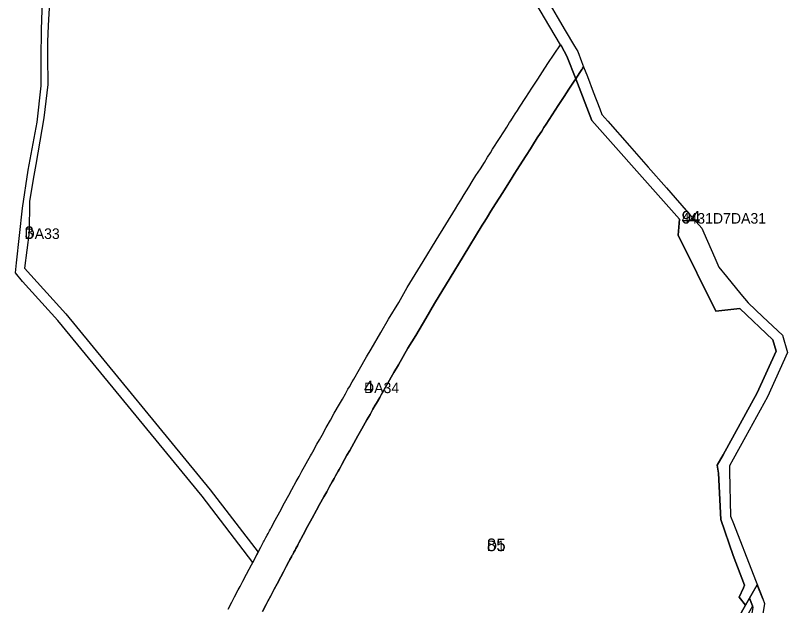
# Model space of a CAD drawing. Extents: x -537012 to -534603, y -1176562 to -1172739.
# Drawn here: x -536018.6 to -535651.7, y -1173694.5 to -1173413.8 of the extents above; entities that cross this region are included whole.
import ezdxf

# ---------------------------------------------------------------- set-up
doc = ezdxf.new("R2010")
doc.units = 0
for name, color, linetype in [('96120023', 7, 'Continuous'), ('96140023', 7, 'Continuous'), ('ID_VPO', 7, 'Continuous'), ('ID_VPS', 7, 'Continuous')]:
    doc.layers.add(name, color=color, linetype=linetype)

msp = doc.modelspace()

# ---------------------------------------------------------------- linework, layer by layer
at = {"layer": '96120023'}
for points in [[(-535666.09, -1173684.66), (-535668.4, -1173688.75), (-535669.68, -1173691), (-535671.6, -1173694.36), (-535674.68, -1173690.42), (-535672.65, -1173686.12), (-535672.1, -1173684.83), (-535677.54, -1173670.61), (-535683.41, -1173653.53), (-535684.54, -1173631.55), (-535685.07, -1173627.77), (-535682.21, -1173622.82), (-535666.13, -1173593.26), (-535657.03, -1173573.52), (-535658.57, -1173568.09), (-535674.26, -1173553.24), (-535685.71, -1173554.4), (-535703.6, -1173518.27), (-535703.03, -1173510.68), (-535711.9, -1173500.73), (-535744.67, -1173463.76), (-535752.34, -1173443.92), (-535751.46, -1173442.6), (-535750.38, -1173440.96), (-535749.69, -1173439.9), (-535749.4, -1173439.46), (-535749.18, -1173439.12), (-535749.05, -1173438.92), (-535748.57, -1173438.22), (-535746.8, -1173442.83), (-535744, -1173450.12), (-535740.92, -1173458.17), (-535739.9, -1173460.82), (-535737.04, -1173464.08), (-535726.71, -1173475.86), (-535717.86, -1173485.95), (-535709.19, -1173495.84), (-535697.78, -1173508.85), (-535692.41, -1173514.97), (-535691.44, -1173517.18), (-535686.26, -1173529.03), (-535684.28, -1173533.55), (-535680.66, -1173537.97), (-535673.84, -1173546.31), (-535670.41, -1173550.5), (-535663.43, -1173557.09), (-535654.08, -1173565.9), (-535651.65, -1173574.09), (-535661.19, -1173595.23), (-535671.63, -1173614.14), (-535677.56, -1173624.89), (-535679.29, -1173628.03), (-535679.23, -1173630.64), (-535678.7, -1173651.88), (-535677.33, -1173655.42), (-535668, -1173679.5), (-535663.42, -1173691.33)], [(-535686.92, -1173727.29), (-535695.05, -1173742.16), (-535697.41, -1173740.24), (-535689.54, -1173725.83), (-535671.6, -1173694.36), (-535669.68, -1173691), (-535668.29, -1173694.6), (-535668.99, -1173695.85)]]:
    msp.add_lwpolyline(points, close=True, dxfattribs=at)
msp.add_lwpolyline([(-535901.19, -1173697.3), (-535899.47, -1173694.01), (-535898.61, -1173692.37), (-535897.31, -1173689.9), (-535895.58, -1173686.61), (-535894.28, -1173684.14), (-535892.54, -1173680.85), (-535891.24, -1173678.38), (-535889.92, -1173675.92), (-535888.62, -1173673.46), (-535888.61, -1173673.44), (-535888.6, -1173673.43), (-535888.59, -1173673.41), (-535888.59, -1173673.4), (-535888.58, -1173673.4), (-535888.58, -1173673.39), (-535888.58, -1173673.38), (-535888.57, -1173673.37), (-535888.56, -1173673.35), (-535888.56, -1173673.34), (-535888.55, -1173673.33), (-535888.16, -1173672.6), (-535887.91, -1173672.13), (-535887.71, -1173671.75), (-535887.43, -1173671.24), (-535887.21, -1173670.83), (-535887.04, -1173670.5), (-535886.84, -1173670.13), (-535886.68, -1173669.83), (-535886.46, -1173669.43), (-535886.31, -1173669.14), (-535885.72, -1173668.05), (-535885.31, -1173667.27), (-535884.96, -1173666.61), (-535884.64, -1173666.01), (-535884.21, -1173665.24), (-535883.86, -1173664.58), (-535881.86, -1173660.91), (-535879.78, -1173656.88), (-535877.58, -1173652.84), (-535875.5, -1173649.17), (-535874.03, -1173646.36), (-535872.01, -1173642.75), (-535870.7, -1173640.37), (-535869.29, -1173637.83), (-535868.07, -1173635.6), (-535867.21, -1173634.07), (-535866.5, -1173632.73), (-535865.29, -1173630.57), (-535864.82, -1173629.72), (-535864.19, -1173628.6), (-535863.82, -1173627.94), (-535863.5, -1173627.33), (-535862.2, -1173625.07), (-535861.04, -1173622.93), (-535859.76, -1173620.67), (-535857.86, -1173617.18), (-535855.84, -1173613.7), (-535854.01, -1173610.34), (-535851.56, -1173606.18), (-535850.1, -1173603.55), (-535848.69, -1173601.04), (-535847.65, -1173599.15), (-535847.04, -1173598.17), (-535845.5, -1173595.47), (-535844.79, -1173594.23), (-535842.03, -1173589.46), (-535838.73, -1173583.65), (-535836.59, -1173579.98), (-535832.07, -1173572.1), (-535828.4, -1173565.98), (-535823.51, -1173557.91), (-535819.48, -1173550.82), (-535812.02, -1173538.6), (-535805.78, -1173528.45), (-535796.72, -1173513.55), (-535795.59, -1173511.7), (-535794.26, -1173509.57), (-535792.64, -1173506.93), (-535790.41, -1173503.44), (-535788.7, -1173500.63), (-535787.04, -1173497.94), (-535784.97, -1173494.7), (-535783.04, -1173491.61), (-535781.54, -1173489.23), (-535780.2, -1173487.12), (-535779.1, -1173485.35), (-535775.95, -1173480.36), (-535773.9, -1173477.22), (-535772.4, -1173474.86), (-535771.12, -1173472.81), (-535770.58, -1173471.97), (-535769.29, -1173469.99), (-535768.51, -1173468.76), (-535767.41, -1173467.11), (-535766.37, -1173465.46), (-535763.47, -1173460.97), (-535760.66, -1173456.57), (-535757.85, -1173452.35), (-535755.58, -1173448.83), (-535753.05, -1173444.98), (-535752.34, -1173443.92), (-535744.67, -1173463.76), (-535711.9, -1173500.73), (-535703.03, -1173510.68), (-535703.6, -1173518.27), (-535685.71, -1173554.4), (-535674.26, -1173553.24), (-535658.57, -1173568.09), (-535657.03, -1173573.52), (-535666.13, -1173593.26), (-535682.21, -1173622.82), (-535685.07, -1173627.77), (-535684.54, -1173631.55), (-535683.41, -1173653.53), (-535677.54, -1173670.61), (-535672.1, -1173684.83), (-535672.65, -1173686.12), (-535674.68, -1173690.42), (-535671.6, -1173694.36), (-535689.54, -1173725.83)], dxfattribs=at)
at = {"layer": '96140023'}
for points in [[(-536002.3, -1173404.63), (-536002.99, -1173418.53), (-536003.38, -1173426.31), (-536003.35, -1173433.33), (-536003.3, -1173446.59), (-536005.11, -1173462.48), (-536008.94, -1173484.69), (-536009.84, -1173489.93), (-536010.81, -1173495.52), (-536011.97, -1173502.26), (-536012.07, -1173516.8), (-536014.28, -1173533.95), (-535994.71, -1173555.65), (-535926, -1173639.4), (-535903.28, -1173669.08), (-535904.02, -1173670.46), (-535905.86, -1173673.94), (-535929.92, -1173642.51), (-535998.5, -1173558.91), (-536015.29, -1173540.29), (-536018.62, -1173536.28), (-536018.08, -1173531.45), (-536015.31, -1173505.45), (-536012.55, -1173487.33), (-536008.37, -1173464.48), (-536006.32, -1173447.22), (-536006.32, -1173434.45), (-536006.31, -1173420.53), (-536005.72, -1173406.73)], [(-535765.58, -1173406.86), (-535761.14, -1173414.39), (-535757.31, -1173420.88), (-535752.87, -1173428.42), (-535751.35, -1173430.99), (-535749.58, -1173435.6), (-535748.57, -1173438.22), (-535749.05, -1173438.92), (-535749.18, -1173439.12), (-535749.4, -1173439.46), (-535749.69, -1173439.9), (-535750.38, -1173440.96), (-535751.46, -1173442.6), (-535752.34, -1173443.92), (-535756.52, -1173433.09), (-535759.12, -1173428.42), (-535759.55, -1173427.69), (-535774.26, -1173402.73)], [(-535917.5, -1173696.14), (-535915.78, -1173692.84), (-535914.49, -1173690.36), (-535912.76, -1173687.06), (-535911.89, -1173685.4), (-535910.59, -1173682.92), (-535908.86, -1173679.62), (-535907.55, -1173677.14), (-535906.46, -1173675.09), (-535905.86, -1173673.94), (-535904.02, -1173670.46), (-535903.28, -1173669.08), (-535903.17, -1173668.87), (-535901.95, -1173666.59), (-535901.85, -1173666.38), (-535900.65, -1173664.14), (-535900.43, -1173663.74), (-535900.25, -1173663.39), (-535900.07, -1173663.07), (-535899.92, -1173662.79), (-535899.7, -1173662.38), (-535899.55, -1173662.09), (-535898.96, -1173660.98), (-535898.55, -1173660.22), (-535898.18, -1173659.52), (-535897.82, -1173658.85), (-535897.4, -1173658.09), (-535897.06, -1173657.45), (-535895.11, -1173653.88), (-535893.03, -1173649.85), (-535890.69, -1173645.55), (-535888.68, -1173642), (-535887.23, -1173639.23), (-535885.13, -1173635.47), (-535883.83, -1173633.11), (-535882.43, -1173630.59), (-535881.19, -1173628.33), (-535880.38, -1173626.87), (-535879.66, -1173625.53), (-535878.39, -1173623.27), (-535877.92, -1173622.41), (-535877.28, -1173621.27), (-535877.01, -1173620.8), (-535876.65, -1173620.11), (-535875.3, -1173617.76), (-535874.16, -1173615.65), (-535872.87, -1173613.38), (-535870.94, -1173609.84), (-535868.92, -1173606.35), (-535867.06, -1173602.94), (-535864.58, -1173598.72), (-535863.19, -1173596.23), (-535861.81, -1173593.77), (-535860.6, -1173591.56), (-535859.92, -1173590.48), (-535858.52, -1173588.01), (-535857.79, -1173586.75), (-535855.05, -1173582), (-535851.73, -1173576.17), (-535849.58, -1173572.47), (-535845.01, -1173564.51), (-535841.25, -1173558.24), (-535836.45, -1173550.32), (-535832.4, -1173543.21), (-535824.81, -1173530.76), (-535818.58, -1173520.62), (-535809.53, -1173505.74), (-535808.34, -1173503.8), (-535807.01, -1173501.67), (-535805.35, -1173498.96), (-535803.13, -1173495.5), (-535801.49, -1173492.81), (-535799.75, -1173489.97), (-535797.64, -1173486.68), (-535795.75, -1173483.65), (-535794.22, -1173481.21), (-535792.89, -1173479.13), (-535791.81, -1173477.39), (-535788.58, -1173472.27), (-535786.52, -1173469.1), (-535785.09, -1173466.85), (-535783.78, -1173464.76), (-535783.18, -1173463.84), (-535781.92, -1173461.89), (-535781.08, -1173460.57), (-535780, -1173458.96), (-535779.02, -1173457.4), (-535776.09, -1173452.86), (-535773.22, -1173448.37), (-535770.39, -1173444.13), (-535768.15, -1173440.65), (-535765.55, -1173436.7), (-535759.55, -1173427.69), (-535759.12, -1173428.42), (-535756.52, -1173433.09), (-535752.34, -1173443.92), (-535753.05, -1173444.98), (-535755.58, -1173448.83), (-535757.85, -1173452.35), (-535760.66, -1173456.57), (-535763.47, -1173460.97), (-535766.37, -1173465.46), (-535767.41, -1173467.11), (-535768.51, -1173468.76), (-535769.29, -1173469.99), (-535770.58, -1173471.97), (-535771.12, -1173472.81), (-535772.4, -1173474.86), (-535773.9, -1173477.22), (-535775.95, -1173480.36), (-535779.1, -1173485.35), (-535780.2, -1173487.12), (-535781.54, -1173489.23), (-535783.04, -1173491.61), (-535784.97, -1173494.7), (-535787.04, -1173497.94), (-535788.7, -1173500.63), (-535790.41, -1173503.44), (-535792.64, -1173506.93), (-535794.26, -1173509.57), (-535795.59, -1173511.7), (-535796.72, -1173513.55), (-535805.78, -1173528.45), (-535812.02, -1173538.6), (-535819.48, -1173550.82), (-535823.51, -1173557.91), (-535828.4, -1173565.98), (-535832.07, -1173572.1), (-535836.59, -1173579.98), (-535838.73, -1173583.65), (-535842.03, -1173589.46), (-535844.79, -1173594.23), (-535845.5, -1173595.47), (-535847.04, -1173598.17), (-535847.65, -1173599.15), (-535848.69, -1173601.04), (-535850.1, -1173603.55), (-535851.56, -1173606.18), (-535854.01, -1173610.34), (-535855.84, -1173613.7), (-535857.86, -1173617.18), (-535859.76, -1173620.67), (-535861.04, -1173622.93), (-535862.2, -1173625.07), (-535863.5, -1173627.33), (-535863.82, -1173627.94), (-535864.19, -1173628.6), (-535864.82, -1173629.72), (-535865.29, -1173630.57), (-535866.5, -1173632.73), (-535867.21, -1173634.07), (-535868.07, -1173635.6), (-535869.29, -1173637.83), (-535870.7, -1173640.37), (-535872.01, -1173642.75), (-535874.03, -1173646.36), (-535875.5, -1173649.17), (-535877.58, -1173652.84), (-535879.78, -1173656.88), (-535881.86, -1173660.91), (-535883.86, -1173664.58), (-535884.21, -1173665.24), (-535884.64, -1173666.01), (-535884.96, -1173666.61), (-535885.31, -1173667.27), (-535885.72, -1173668.05), (-535886.31, -1173669.14), (-535886.46, -1173669.43), (-535886.68, -1173669.83), (-535886.84, -1173670.13), (-535887.04, -1173670.5), (-535887.21, -1173670.83), (-535887.43, -1173671.24), (-535887.71, -1173671.75), (-535887.91, -1173672.13), (-535888.16, -1173672.6), (-535888.55, -1173673.33), (-535888.56, -1173673.34), (-535888.56, -1173673.35), (-535888.57, -1173673.37), (-535888.58, -1173673.38), (-535888.58, -1173673.39), (-535888.58, -1173673.4), (-535888.59, -1173673.4), (-535888.59, -1173673.41), (-535888.6, -1173673.43), (-535888.61, -1173673.44), (-535888.62, -1173673.46), (-535889.92, -1173675.92), (-535891.24, -1173678.38), (-535892.54, -1173680.85), (-535894.28, -1173684.14), (-535895.58, -1173686.61), (-535897.31, -1173689.9), (-535898.61, -1173692.37), (-535899.47, -1173694.01), (-535901.19, -1173697.3)]]:
    msp.add_lwpolyline(points, dxfattribs=at)
for points in [[(-535666.09, -1173684.66), (-535668.4, -1173688.75), (-535669.68, -1173691), (-535671.6, -1173694.36), (-535674.68, -1173690.42), (-535672.65, -1173686.12), (-535672.1, -1173684.83), (-535677.54, -1173670.61), (-535683.41, -1173653.53), (-535684.54, -1173631.55), (-535685.07, -1173627.77), (-535682.21, -1173622.82), (-535666.13, -1173593.26), (-535657.03, -1173573.52), (-535658.57, -1173568.09), (-535674.26, -1173553.24), (-535685.71, -1173554.4), (-535703.6, -1173518.27), (-535703.03, -1173510.68), (-535711.9, -1173500.73), (-535744.67, -1173463.76), (-535752.34, -1173443.92), (-535751.46, -1173442.6), (-535750.38, -1173440.96), (-535749.69, -1173439.9), (-535749.4, -1173439.46), (-535749.18, -1173439.12), (-535749.05, -1173438.92), (-535748.57, -1173438.22), (-535746.8, -1173442.83), (-535744, -1173450.12), (-535740.92, -1173458.17), (-535739.9, -1173460.82), (-535737.04, -1173464.08), (-535726.71, -1173475.86), (-535717.86, -1173485.95), (-535709.19, -1173495.84), (-535697.78, -1173508.85), (-535692.41, -1173514.97), (-535691.44, -1173517.18), (-535686.26, -1173529.03), (-535684.28, -1173533.55), (-535680.66, -1173537.97), (-535673.84, -1173546.31), (-535670.41, -1173550.5), (-535663.43, -1173557.09), (-535654.08, -1173565.9), (-535651.65, -1173574.09), (-535661.19, -1173595.23), (-535671.63, -1173614.14), (-535677.56, -1173624.89), (-535679.29, -1173628.03), (-535679.23, -1173630.64), (-535678.7, -1173651.88), (-535677.33, -1173655.42), (-535668, -1173679.5), (-535663.42, -1173691.33)], [(-535689.01, -1173747.62), (-535692.64, -1173743.73), (-535673.33, -1173725.68), (-535671.95, -1173718.08), (-535667.97, -1173695.42), (-535668.29, -1173694.6), (-535669.68, -1173691), (-535668.4, -1173688.75), (-535666.09, -1173684.66), (-535663.42, -1173691.33), (-535662.56, -1173693.55), (-535664.98, -1173708.05), (-535668.03, -1173726.35), (-535668.3, -1173727.97), (-535688.76, -1173747.02)]]:
    msp.add_lwpolyline(points, close=True, dxfattribs=at)

# ---------------------------------------------------------------- texts
at = {"layer": '96120023'}
for s, p in [('4431D7DA31', (-535702, -1173512.78)), ('D1', (-535794.58, -1173668.58))]:
    msp.add_text(s, height=5, rotation=0, dxfattribs=at).set_placement(p)
at = {"layer": '96140023'}
for s, rotation, p in [('4431D7DA31', 0, (-535702, -1173512.78)), ('DA33', 360, (-536014.29, -1173520.08)), ('DA34', 360, (-535852.95, -1173593.43))]:
    msp.add_text(s, height=5, rotation=rotation, dxfattribs=at).set_placement(p)
at = {"layer": 'ID_VPO'}
for s, rotation, p in [('94', 0, (-535702, -1173512.78)), ('3', 360, (-536014.29, -1173520.08)), ('4', 360, (-535852.95, -1173593.43))]:
    msp.add_text(s, height=6, rotation=rotation, dxfattribs=at).set_placement(p)
at = {"layer": 'ID_VPS'}
for s, rotation, p in [('94', 0, (-535702, -1173512.78)), ('85', 360, (-535794.58, -1173668.58))]:
    msp.add_text(s, height=6, rotation=rotation, dxfattribs=at).set_placement(p)

doc.saveas('drawing.dxf')
